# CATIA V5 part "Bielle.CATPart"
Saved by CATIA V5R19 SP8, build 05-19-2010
Part number: Bielle
Bounding box of the stored display mesh (mm): x 0 to 5, y -30.976 to 2.855, z -86.987 to 2.987
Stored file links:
  C:\Users\ThinkMotion\Desktop\EU_thinkMotion\iao\IAO_MMS_Groupe3\pmayet\pmayet_avant_optimisation\pmayet_avant_optimisation\Bielle.CATPart
  C:\Users\ThinkMotion\Desktop\EU_thinkMotion\iao\IAO_MMS_Groupe3\pmayet\pmayet_avant_optimisation\pmayet_avant_optimisation\pmayet.CATProduct
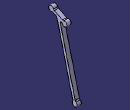
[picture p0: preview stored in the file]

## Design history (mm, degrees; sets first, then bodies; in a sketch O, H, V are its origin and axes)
Parameters
  Largeur_bielle = 3 mm
  Rayon_axe = 1.5 mm
  Longueur_axe = 3.5 mm
  Epaisseur_bielle = 5 mm
Set1
  Plane1: linked copy from another document
  Line1: linked copy from another document
  Point1 "Point2": linked copy from another document
  Point2 "Point3": linked copy from another document
  Point3 "PointB": linked copy from another document
  Line2: linked copy from another document
Body1 (main body)
  Sketch1 on Plane1, origin (0, 0, 0), H (0, 1, 0), V (0, 0, 1)
    line L1 (-24.1354, -0.2552) -> (-14.5229, -5.0615)
    point P1 (-25.0054, 0.1797)
    point P2 (-13.653, -5.4965)
    line L2 (-15.8091, -7.7725) -> (-15.6708, -7.8416)
    point P3 (-17.7538, -6.8002)
    point P4 (-14.9946, -8.1797)
    line L3 (-25.4771, -2.9385) -> (-22.1106, -4.6217)
    point P5 (-26.347, -2.5035)
    point P6 (-21.2879, -5.0331)
    reference projected line E1 (-28, 0) -> (-12, -8) from Line1
    reference projected line E2 (-28, 0) -> (-12, -8) from Line1
    arc A1 centre (-12, -8) radius 3 from (-14.8944, -8.7889) to (-12.9771, -5.1636) ccw
    point P7 (-12, -8)
    point P8 (-14.9946, -8.1797)
    point P9 (-13.653, -5.4965)
    reference projected point E3 (-12, -8) from Point2
    arc A2 centre (-28, 0) radius 3 from (-25.1446, 0.9202) to (-27.0229, -2.8364) ccw
    point P10 (-28, 0)
    point P11 (-25.0054, 0.1797)
    point P12 (-26.347, -2.5035)
    reference projected point E4 (-28, 0) from Point1
    arc A3 centre (0, -84) radius 3 from (-2.5569, -82.4309) to (1.5177, -81.4122) ccw
    point P13 (0, -84)
    point P14 (-2.0853, -81.8433)
    point P15 (0.8251, -81.1157)
    reference projected point E5 (0, -84) from Point3
    reference projected line E6 (-28, 0) -> (-12, -8) from Line1
    reference projected line E7 (-28, 0) -> (-12, -8) from Line1
    reference projected line E8 (-28, 0) -> (-12, -8) from Line1
    reference projected line E9 (-28, 0) -> (-12, -8) from Line1
    line L4 (-21.0648, -5.9255) -> (-2.3212, -80.8997)
    point P16 (-21.2879, -5.0331)
    point P17 (-2.0853, -81.8433)
    line L5 (-17.2265, -8.9095) -> (0.5892, -80.1721)
    point P18 (-17.7538, -6.8002)
    point P19 (0.8251, -81.1157)
    reference projected line E10 (-20, -4) -> (0.4709, -85.8837) from Line2
    reference projected line E11 (-20, -4) -> (0.4709, -85.8837) from Line2
    reference projected line E12 (-20, -4) -> (0.4709, -85.8837) from Line2
    reference projected line E13 (-20, -4) -> (0.4709, -85.8837) from Line2
    arc A4 centre (-23.241, 1.5336) radius 2 from (-25.1446, 0.9202) to (-24.1354, -0.2552) ccw
    arc A5 centre (-13.6285, -3.2726) radius 2 from (-12.9771, -5.1636) to (-14.5229, -5.0615) cw
    arc A6 centre (-26.3715, -4.7274) radius 2 from (-27.0229, -2.8364) to (-25.4771, -2.9385) cw
    arc A7 centre (-16.3416, -9.1833) radius 1.5 from (-14.8944, -8.7889) to (-15.6708, -7.8416) ccw
    arc A8 centre (-23.0051, -6.4106) radius 2 from (-22.1106, -4.6217) to (-21.0648, -5.9255) cw
    arc A9 centre (-16.2563, -8.6669) radius 1 from (-17.2265, -8.9095) to (-15.8091, -7.7725) cw
    arc A10 centre (-4.2615, -81.3848) radius 2 from (-2.5569, -82.4309) to (-2.3212, -80.8997) ccw
    arc A11 centre (2.5295, -79.687) radius 2 from (1.5177, -81.4122) to (0.5892, -80.1721) cw
    distance E1 L1 = 1.5 {= Largeur_bielle /2}
    radius A1 = 3 {= Rayon_axe *2}
    radius A2 = 3 {= Rayon_axe *2}
    radius A3 = 3 {= Rayon_axe *2}
    distance E6 L3 = 1.5 {= Largeur_bielle /2}
    distance E8 L2 = 1.5 {= Largeur_bielle /2}
    distance E10 L4 = 1.5 {= Largeur_bielle /2}
    distance E12 L5 = 1.5 {= Largeur_bielle /2}
    radius A4 = 2
    radius A5 = 2
    radius A6 = 2
    radius A7 = 1.5
    radius A8 = 2
    radius A9 = 1
    radius A10 = 2
    radius A11 = 2
    parallelism: E2 L1, E7 L3, E9 L2, E11 L4, E13 L5
    coincidence: E3 P7, P2 P9, P10 E4, P11 P1, E5 P13, P12 P5, P8 P4, P6 P16, P17 P14, P18 P3, P19 P15, A2 P11, L1 P1, A1 P9, L1 P2, A2 P12, L3 P5, A1 P8, L2 P4, L3 P6, L4 P16, L5 P18, L2 P3, A3 P14, L4 P17, A3 P15, L5 P19
    tangency: A4 A2, A4 L1, A5 L1, A5 A1, A6 A2, A6 L3, A7 L2, A7 A1, A8 L3, A8 L4, A9 L5, A9 L2, A10 L4, A10 A3, A11 L5, A11 A3
  Pad1: profile Sketch1, direction (1, 0, 0), length 5 {= Epaisseur_bielle}
  Sketch2 on Plane1, origin (0, 0, 0), H (0, 1, 0), V (0, 0, 1)
    circle A1 centre (-28, 0) radius 1.5
    point P1 (-28, 0)
    reference projected point E1 (-28, 0) from Point1
    circle A2 centre (-12, -8) radius 1.5
    point P2 (-12, -8)
    reference projected point E2 (-12, -8) from Point2
    circle A3 centre (0, -84) radius 1.5
    point P3 (0, -84)
    reference projected point E3 (0, -84) from Point3
    distance A1 P1 = 1.5 {= Rayon_axe}
    distance A2 P2 = 1.5 {= Rayon_axe}
    distance A3 P3 = 1.5 {= Rayon_axe}
    coincidence: E1 P1, E2 P2, E3 P3
  Pocket1: profile Sketch2, direction (1, 0, 0), length 3.5 {= Longueur_axe}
